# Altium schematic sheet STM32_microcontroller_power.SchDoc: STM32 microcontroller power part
size A4; Date: Not used; ApprovedBy: Not used; CheckedBy: Not used; Author: Not used; CompanyName: STMicroelectronics; DrawnBy: Not used; Engineer: Not used; Organization: Not used; Address1: Not used; Address2: Not used; Address3: Not used; Address4: Not used; DocumentNumber: 4; Revision: Not used; SheetNumber: 4; SheetTotal: 8
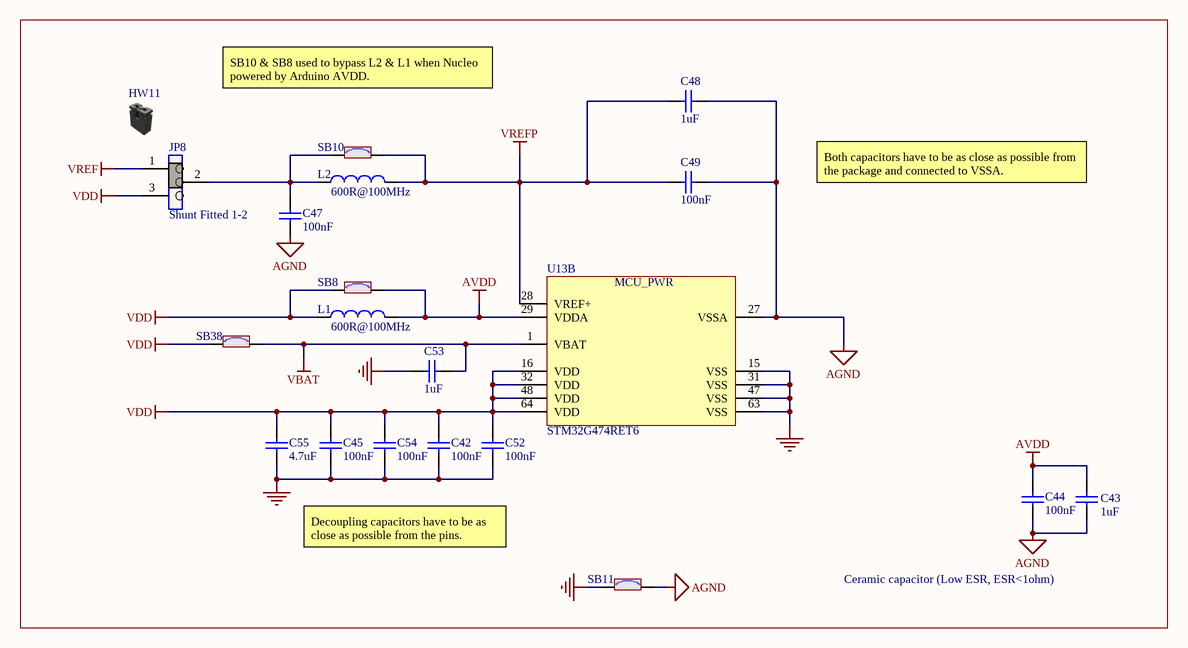
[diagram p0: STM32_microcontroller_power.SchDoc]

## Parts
C42  value 100nF  [C0402]
C43  value 1uF  [C0603]
C44  value 100nF  [C0402]
C45  value 100nF  [C0402]
C47  value 100nF  [C0402]
C48  value 1uF  [C0603]
C49  value 100nF  [C0402]
C52  value 100nF  [C0402]
C53  value 1uF  [C0603]
C54  value 100nF  [C0402]
C55  value 4.7uF  [C0603]
HW11  (no value)  (mechanical)
JP8  Shunt Fitted 1-2  [CON_SAMTEC_TSW-103-07-F-S]
L1  value 600R@100MHz  [L0603]
L2  value 600R@100MHz  [L0603]
SB8  (no value)  [SOLDER-BRIDGE_R0603-0R]
SB10  (no value)  [SOLDER-BRIDGE_R0603-0R]
SB11  (no value)  [SOLDER-BRIDGE_R0603-0R]
SB38  (no value)  [SOLDER-BRIDGE_R0603-0R]
U13  value STM32G474RET6  [ICC_LQFP64_10X10_P050_SOCKET_YAMAICHI_IC149-064-069-B5_NM]  (hidden comment: STM32G4xx_LQFP64)  (part B of 2)

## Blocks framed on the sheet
Ceramic capacitor (Low ESR, ESR<1ohm): C42-C45 C47-C49 C52-C55 HW11 JP8 L1 L2 SB8 SB10 SB11 SB38 U13

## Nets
AGND: C43.1 C44.1 C47.1 C48.2 C49.2 SB11.2 U13.27(VSSA)
AVDD: C43.2 C44.2 L1.2 SB8.2 U13.29(VDDA)
GND: C42.1 C45.1 C52.1 C53.1 C54.1 C55.1 SB11.1 U13.15(VSS) U13.31(VSS) U13.47(VSS) U13.63(VSS)
VBAT: C53.2 SB38.2 U13.1(VBAT)
VDD: C42.2 C45.2 C52.2 C54.2 C55.2 JP8.3 L1.1 SB8.1 SB38.1 U13.16(VDD) U13.32(VDD) U13.48(VDD) U13.64(VDD)
VREF: JP8.1
VREFP: C48.1 C49.1 L2.2 SB10.2 U13.28(VREF+)
NetC47_2: C47.2 JP8.2 L2.1 SB10.1

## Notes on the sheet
- SB10 & SB8 used to bypass L2 & L1 when Nucleo powered by Arduino AVDD.
- Both capacitors have to be as close as possible from the package and connected to VSSA.
- Decoupling capacitors have to be as close as possible from the pins.

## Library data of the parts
C42 C44 C45 C47 C49 C52 C54 = MCD-00102: Capacitor, MLCC, 100nF, 16V, X7R, 10%, 0402, T=0,5mm; Manufacturer_Part_Number: CC0402KRX7R7BB104; Manufacturer: YAGEO; Provided_By: Subcon; Initial_Board_Reference: MB1262
C43 C48 C53 = MCD-00010: Capacitor, MLCC, 1uF, 16V, X5R, 10%, 0603, T=0,8mm; Manufacturer_Part_Number: CC0603KRX5R7BB105; Manufacturer: YAGEO; Provided_By: Subcon; Initial_Board_Reference: MB1274
C55 = MCD-00009: Capacitor, MLCC, 4.7uF, 16V, X5R, 10%, 0603, T=0.8mm; Manufacturer_Part_Number: CC0603KRX5R7BB475; Manufacturer: YAGEO; Provided_By: subcon; Initial_Board_Reference: MB1274
HW11 = MCD-00043: SHUNT 2.54mm BLACK; Manufacturer_Part_Number: SNT-100-BK-G; Manufacturer: SAMTEC; Part_Type: Mechanical; Provided_By: Subcon; Initial_Board_Reference: MB1274
JP8 = MCD-00684: Header, 3x1, 2,54mm, VR, TH, Height 5.84mm/2.54mm - Shunt Fitted 1-2 by default; Part_Type: Connector; Manufacturer_Part_Number: TSW-103-07-F-S; Manufacturer: SAMTEC; Provided_By: Subcon; Initial_Board_Reference: MB1331
L1 L2 = MCD-00047: SMD Chip ferrite bead, 600R@100MHz +/-25%, 350mA, 500mohm DC, 0603, T=0.8mm; Part_Type: Inductor; Manufacturer_Part_Number: FCM1608KF-601T03; Manufacturer: TAI-TECH; Provided_By: Subcon; Initial_Board_Reference: MB1274
SB8 SB10 SB11 SB38 = MCD-00071: Solder Bridge ON; Part_Type: Mechanical; Provided_By: Subcon; Initial_Board_Reference: MB1274
U13 = MCD-01243: STM32G474, LQFP64 package,  3D IC footprint with 2D socket footprint.; Manufacturer: STMICROELECTRONICS; Provided_By: SUBCO with ST control; Initial_Board_Reference: MB1367; Item Type: Item; Path: ws/MCD_ApplicationBoards/Lists/MCDPARTSdatabase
